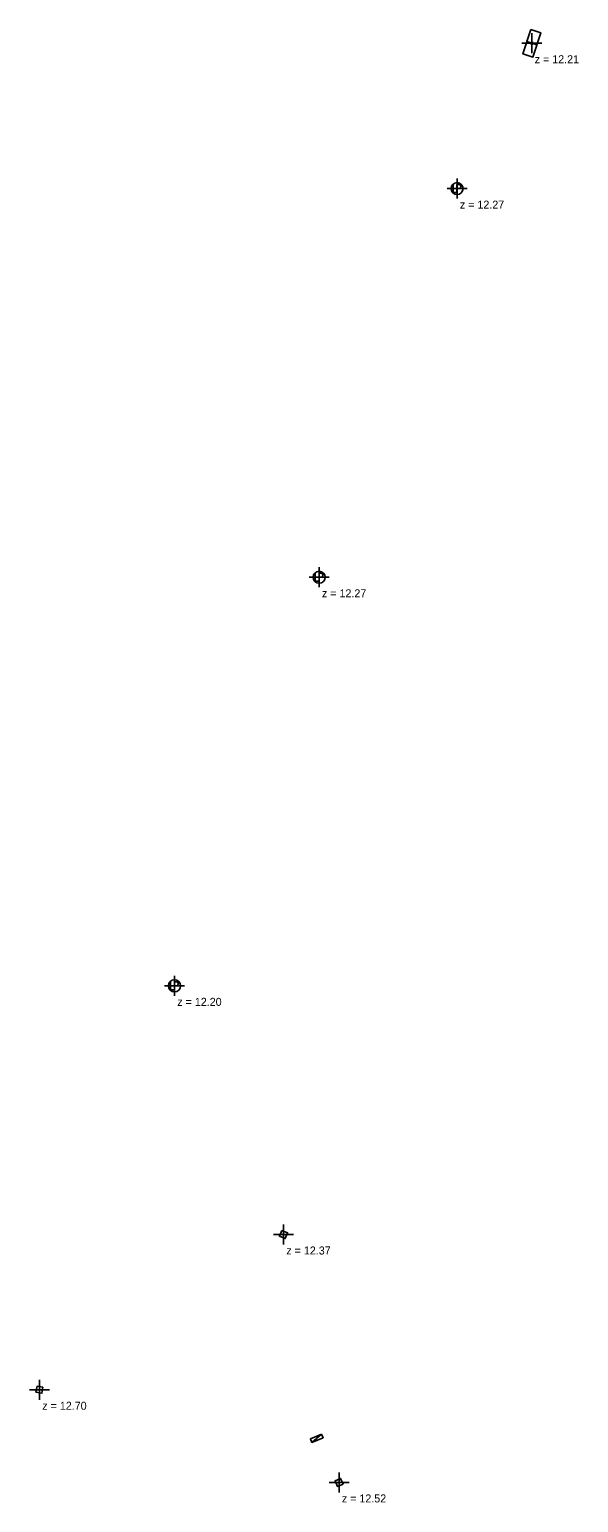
# Model space of a CAD drawing. Extents: x 377004.1 to 377031.6, y 296641.8 to 296715.5.
import ezdxf

# ---------------------------------------------------------------- set-up
doc = ezdxf.new("R2010")
doc.units = 0
for name, color, linetype in [('PGOC_BT_CONSTRUIT', 7, 'Continuous'), ('PtLambert+coord_', 7, 'Continuous'), ('SymbolesFixes', 7, 'Continuous')]:
    doc.layers.add(name, color=color, linetype=linetype)

msp = doc.modelspace()

# ---------------------------------------------------------------- linework, layer by layer
at = {"layer": 'PGOC_BT_CONSTRUIT'}
msp.add_line((377018.256, 296644.831), (377018.731, 296645.249), dxfattribs=at)
msp.add_lwpolyline([(377018.731, 296645.249), (377018.178, 296645.015), (377018.256, 296644.831), (377018.809, 296645.065)], close=True, dxfattribs=at)
at = {"layer": 'PtLambert+coord_'}
for points in [[(377029.243, 296715.289), (377029.243, 296714.789), (377029.743, 296714.789)], [(377028.743, 296714.789), (377029.243, 296714.789), (377029.243, 296714.289)], [(377025.005, 296707.521), (377025.505, 296707.521), (377025.505, 296707.021)], [(377025.505, 296708.021), (377025.505, 296707.521), (377026.005, 296707.521)], [(377018.614, 296688.589), (377018.614, 296688.089), (377019.114, 296688.089)], [(377018.114, 296688.089), (377018.614, 296688.089), (377018.614, 296687.589)], [(377011.387, 296668.162), (377011.387, 296667.662), (377011.887, 296667.662)], [(377010.887, 296667.662), (377011.387, 296667.662), (377011.387, 296667.162)], [(377016.334, 296655.23), (377016.834, 296655.23), (377016.834, 296654.73)], [(377016.834, 296655.73), (377016.834, 296655.23), (377017.334, 296655.23)], [(377004.643, 296647.968), (377004.643, 296647.468), (377005.143, 296647.468)], [(377004.143, 296647.468), (377004.643, 296647.468), (377004.643, 296646.968)], [(377019.108, 296642.834), (377019.608, 296642.834), (377019.608, 296642.334)], [(377019.608, 296643.334), (377019.608, 296642.834), (377020.108, 296642.834)]]:
    msp.add_lwpolyline(points, dxfattribs=at)
at = {"layer": 'SymbolesFixes'}
msp.add_line((377029.493, 296714.708), (377028.993, 296714.869), dxfattribs=at)
for points in [[(377029.189, 296715.479), (377028.797, 296714.26), (377029.297, 296714.099), (377029.689, 296715.318)], [(377029.232, 296714.849), (377029.199, 296714.747), (377029.255, 296714.729), (377029.287, 296714.831)], [(377016.746, 296655.437), (377016.627, 296655.143), (377016.921, 296655.024), (377017.04, 296655.318)], [(377004.818, 296647.589), (377004.523, 296647.644), (377004.468, 296647.348), (377004.763, 296647.293)], [(377019.808, 296642.753), (377019.689, 296643.035), (377019.408, 296642.915), (377019.527, 296642.634)]]:
    msp.add_lwpolyline(points, close=True, dxfattribs=at)
for points in [[(377025.311, 296707.721), (377025.311, 296707.321), (377025.481, 296707.321)], [(377025.501, 296707.321), (377025.501, 296707.721), (377025.621, 296707.721), (377025.657, 296707.705), (377025.687, 296707.643), (377025.687, 296707.605), (377025.659, 296707.541), (377025.621, 296707.525), (377025.501, 296707.525)], [(377018.42, 296688.289), (377018.42, 296687.889), (377018.59, 296687.889)], [(377018.61, 296687.889), (377018.61, 296688.289), (377018.73, 296688.289), (377018.766, 296688.273), (377018.796, 296688.211), (377018.796, 296688.173), (377018.768, 296688.109), (377018.73, 296688.093), (377018.61, 296688.093)], [(377011.193, 296667.862), (377011.193, 296667.462), (377011.363, 296667.462)], [(377011.383, 296667.462), (377011.383, 296667.862), (377011.503, 296667.862), (377011.539, 296667.846), (377011.569, 296667.784), (377011.569, 296667.746), (377011.541, 296667.682), (377011.503, 296667.666), (377011.383, 296667.666)]]:
    msp.add_lwpolyline(points, dxfattribs=at)
for centre in [(377025.505, 296707.521), (377018.614, 296688.089), (377011.387, 296667.662)]:
    msp.add_circle(centre, 0.3, dxfattribs=at)

# ---------------------------------------------------------------- texts
at = {"layer": 'PtLambert+coord_'}
for s, p in [('z = 12.21', (377029.383, 296713.789)), ('z = 12.27', (377025.645, 296706.521)), ('z = 12.27', (377018.754, 296687.089)), ('z = 12.20', (377011.527, 296666.662)), ('z = 12.37', (377016.974, 296654.23)), ('z = 12.70', (377004.783, 296646.468)), ('z = 12.52', (377019.748, 296641.834))]:
    msp.add_text(s, height=0.4, dxfattribs=at).set_placement(p)

doc.saveas('drawing.dxf')
